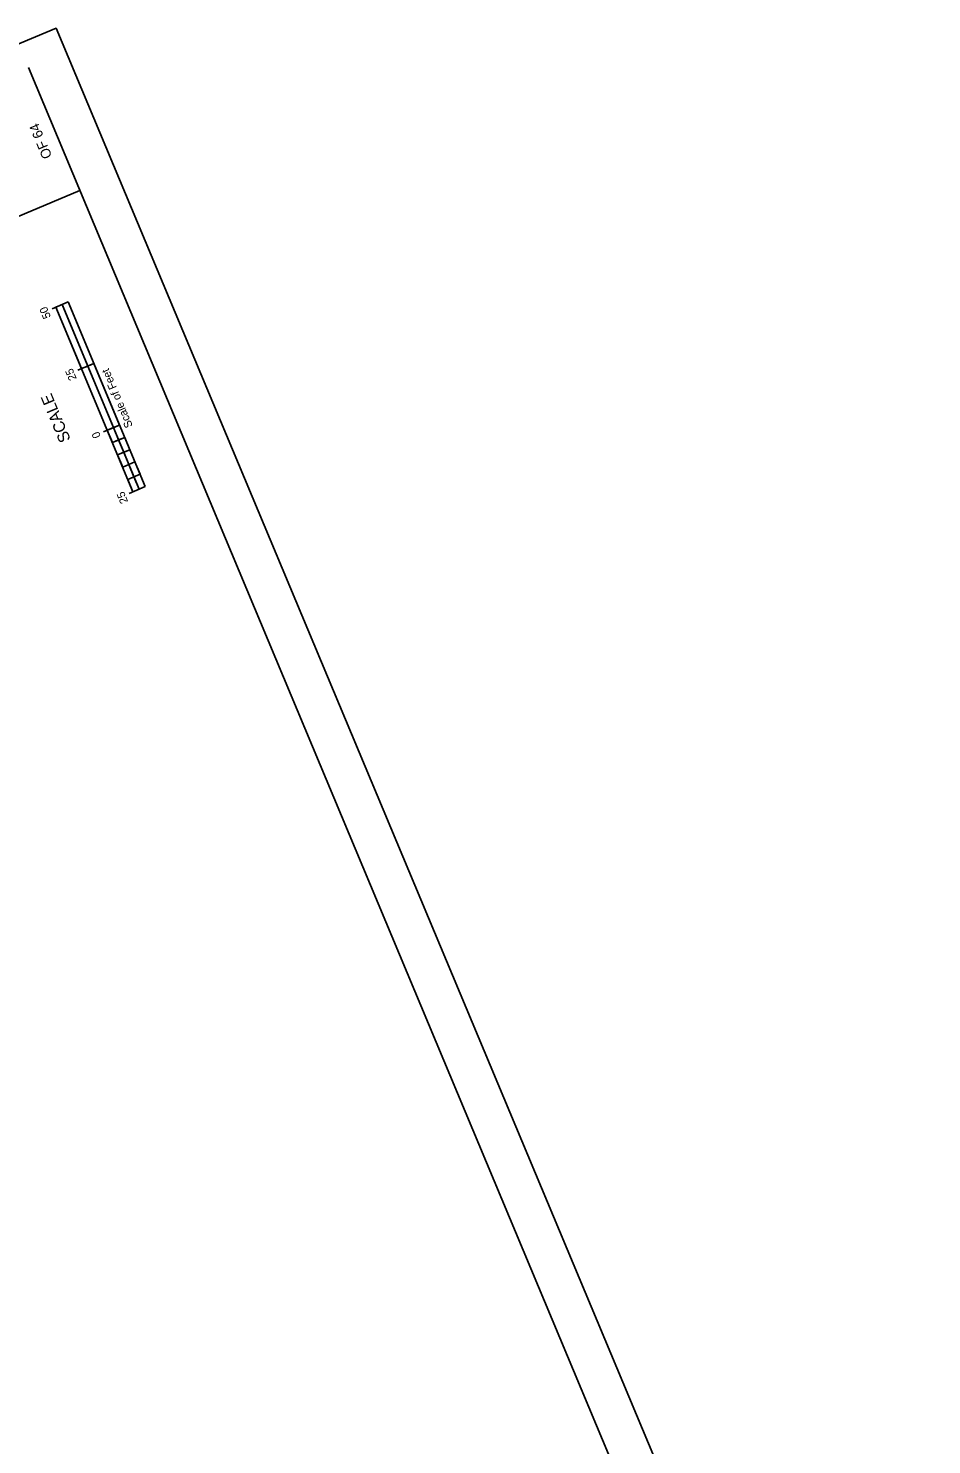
# Model space of a CAD drawing. Extents: x 1111244 to 1112080, y 617020 to 618016.
# Drawn here: x 1111741 to 1112080, y 617485 to 618016 of the extents above; entities that cross this region are included whole.
import ezdxf

# ---------------------------------------------------------------- set-up
doc = ezdxf.new("R2010")
doc.units = 0
for name, color, linetype in [('BORDER', 7, 'Continuous'), ('Default', 7, 'Continuous'), ('H_V CONTROLS', 7, 'Continuous'), ('PLOT BOUNDARY', 7, 'Continuous')]:
    doc.layers.add(name, color=color, linetype=linetype)

msp = doc.modelspace()

# ---------------------------------------------------------------- linework, layer by layer
at = {"layer": 'BORDER'}
for p, q in [((1112050.29, 617263.43), (1111741.35, 618001.37)), ((1111760.64, 617955.24), (1111276.37, 617752.5))]:
    msp.add_line(p, q, dxfattribs=at)
at = {"layer": 'Default'}
msp.add_lwpolyline([(1111572.69, 617019.61), (1111244.44, 617803.67), (1111751.77, 618016.07), (1112080.02, 617232.01)], close=True, dxfattribs=at)
at = {"layer": 'H_V CONTROLS'}
for p, q in [((1111756.27, 617913.52), (1111750.22, 617910.99)), ((1111756.27, 617913.52), (1111785.19, 617844.32)), ((1111780.57, 617842.39), (1111751.66, 617911.59)), ((1111782.88, 617843.36), (1111753.97, 617912.56)), ((1111765.91, 617890.45), (1111759.86, 617887.92)), ((1111769.49, 617864.86), (1111775.55, 617867.39)), ((1111777.48, 617862.77), (1111772.86, 617860.85)), ((1111779.4, 617858.16), (1111774.79, 617856.23)), ((1111781.33, 617853.55), (1111776.72, 617851.62)), ((1111783.26, 617848.93), (1111778.64, 617847.01)), ((1111785.19, 617844.32), (1111779.13, 617841.79))]:
    msp.add_line(p, q, dxfattribs=at)
for points in [[(1111763.6, 617889.49), (1111753.97, 617912.56), (1111751.66, 617911.59), (1111761.3, 617888.53), (1111763.6, 617889.49)], [(1111763.6, 617889.49), (1111773.24, 617866.42), (1111775.55, 617867.39), (1111765.91, 617890.45), (1111763.6, 617889.49)], [(1111775.17, 617861.81), (1111773.24, 617866.42), (1111770.93, 617865.46), (1111772.86, 617860.85), (1111775.17, 617861.81)], [(1111777.1, 617857.2), (1111779.4, 617858.16), (1111777.48, 617862.77), (1111775.17, 617861.81), (1111777.1, 617857.2)], [(1111777.1, 617857.2), (1111774.79, 617856.23), (1111776.72, 617851.62), (1111779.02, 617852.58), (1111777.1, 617857.2)], [(1111780.95, 617847.97), (1111783.26, 617848.93), (1111781.33, 617853.55), (1111779.02, 617852.58), (1111780.95, 617847.97)], [(1111780.95, 617847.97), (1111778.64, 617847.01), (1111780.57, 617842.39), (1111782.88, 617843.36), (1111780.95, 617847.97)]]:
    msp.add_lwpolyline(points, dxfattribs=at)
at = {"layer": 'PLOT BOUNDARY'}
msp.add_lwpolyline([(1112080.02, 617232.01), (1111751.77, 618016.07), (1111244.44, 617803.67), (1111572.69, 617019.61)], close=True, dxfattribs=at)

# ---------------------------------------------------------------- texts
at = {"layer": 'BORDER'}
msp.add_text('OF 64', height=3.726, rotation=112.7167, dxfattribs=at).set_placement((1111750.33, 617968.09))
at = {"layer": 'H_V CONTROLS'}
for s, height, p in [('50', 3, (1111749.87, 617907.94)), ('25', 3, (1111759.54, 617884.79)), ('Scale of Feet', 3, (1111780.57, 617867.04)), ('SCALE', 4.375, (1111757.3, 617861.95)), ('0', 3, (1111768.57, 617863.17)), ('25', 3, (1111778.81, 617838.66))]:
    msp.add_text(s, height=height, rotation=112.6747, dxfattribs=at).set_placement(p)

doc.saveas('drawing.dxf')
